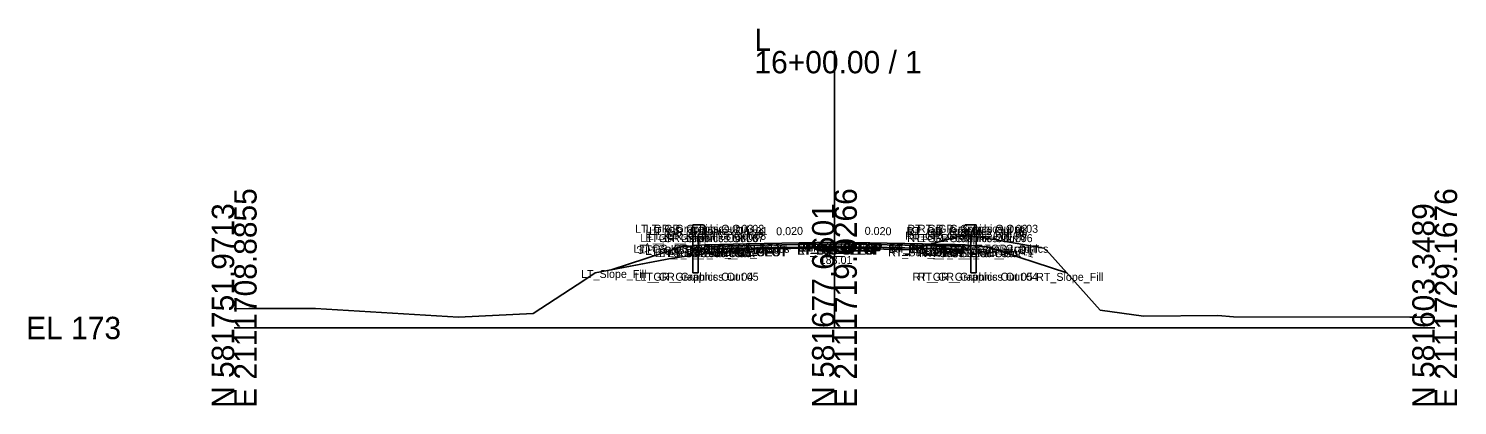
# Model space of a CAD drawing. Extents: x -486 to 1153, y -333 to 9539.
# Drawn here: x -25.7 to 152.8, y 6490.3 to 6537.5 of the extents above; entities that cross this region are included whole.
import ezdxf

# ---------------------------------------------------------------- set-up
doc = ezdxf.new("R2010")
doc.units = 0
for name, color, linetype in [('Default', 7, 'Continuous'), ('Exist Cross Section Cell', 7, 'Continuous'), ('Exist XS Ground Line', 7, 'Continuous'), ('Prop CMT Guardrail Graphics', 7, 'Continuous'), ('Prop CMT Pvmt Course 1', 7, 'Continuous'), ('Prop CMT Pvmt Course 2', 7, 'Continuous'), ('Prop CMT Pvmt Course 3', 7, 'Continuous'), ('Prop CMT Pvmt Surface', 7, 'Continuous'), ('Prop CMT Pvmt Surface Shoulder', 7, 'Continuous'), ('Prop CMT Shld Paved Course 1', 7, 'Continuous'), ('Prop CMT Shld Paved Course 2', 7, 'Continuous'), ('Prop CMT Shld Paved Course 3', 7, 'Continuous'), ('Prop CMT Slope Grass', 7, 'Continuous'), ('Prop CMT Subgrade Earthwork', 7, 'Continuous'), ('Prop XS Earthwork Shape', 7, 'Continuous'), ('Prop XS SE Text', 7, 'Continuous'), ('Prop XS Side Slope Text', 7, 'Continuous'), ('Scratch_Level_0', 7, 'Continuous')]:
    doc.layers.add(name, color=color, linetype=linetype)

msp = doc.modelspace()

# ---------------------------------------------------------------- linework, layer by layer
at = {"layer": 'Exist Cross Section Cell'}
for p, q in [((75, 6500), (75, 6534.66)), ((0, 6500), (75, 6500)), ((75, 6500), (150, 6500))]:
    msp.add_line(p, q, dxfattribs=at)
at = {"layer": 'Exist XS Ground Line'}
for p, q in [((84.43, 6509.78), (90.88, 6511.55)), ((90.88, 6511.55), (93.31, 6511.35)), ((93.31, 6511.35), (101.16, 6509.99)), ((57.72, 6509.17), (65.45, 6509.9)), ((65.45, 6509.9), (66.96, 6509.91)), ((66.96, 6509.91), (74.77, 6510.01)), ((74.77, 6510.01), (76.35, 6509.98)), ((76.35, 6509.98), (84.43, 6509.78)), ((101.16, 6509.99), (101.86, 6509.33)), ((101.86, 6509.33), (108.19, 6502.21)), ((45.1, 6506.88), (54.75, 6508.75)), ((54.75, 6508.75), (57.72, 6509.17)), ((37.37, 6501.8), (43.83, 6506.03)), ((43.83, 6506.03), (45.1, 6506.88)), ((0, 6502.38), (1.82, 6502.42)), ((1.82, 6502.42), (10.14, 6502.43)), ((10.14, 6502.43), (28.03, 6501.34)), ((108.19, 6502.21), (113.61, 6501.48)), ((28.03, 6501.34), (37.37, 6501.8)), ((113.61, 6501.48), (122.91, 6501.58)), ((122.91, 6501.58), (124.87, 6501.41)), ((124.87, 6501.41), (146.9, 6501.34)), ((146.9, 6501.34), (147.49, 6501.35)), ((147.49, 6501.35), (148.14, 6501.36)), ((148.14, 6501.36), (148.51, 6501.35)), ((148.51, 6501.35), (150, 6501.31))]:
    msp.add_line(p, q, dxfattribs=at)
at = {"layer": 'Prop CMT Guardrail Graphics'}
for points in [[(57.3, 6506.91), (57.3, 6512.91)], [(57.3, 6512.91), (58.63, 6512.91), (58.9, 6512.62)], [(92.7, 6512.91), (91.37, 6512.91), (91.1, 6512.62)], [(92.7, 6506.91), (92.7, 6512.91)], [(58.9, 6512.03), (58.63, 6511.74), (57.96, 6511.74)], [(57.96, 6511.74), (57.96, 6506.91)], [(58.9, 6512.62), (58.63, 6512.32)], [(58.63, 6512.32), (58.9, 6512.03)], [(91.1, 6512.62), (91.37, 6512.32)], [(91.37, 6512.32), (91.1, 6512.03)], [(91.1, 6512.03), (91.37, 6511.74), (92.04, 6511.74)], [(92.04, 6511.74), (92.04, 6506.91)], [(57.96, 6506.91), (57.3, 6506.91)], [(92.04, 6506.91), (92.7, 6506.91)]]:
    msp.add_lwpolyline(points, dxfattribs=at)
at = {"layer": 'Prop CMT Pvmt Course 1'}
for points in [[(75, 6510.74), (64, 6510.52)], [(64, 6510.31), (75, 6510.53)], [(64, 6510.52), (64, 6510.31)], [(75, 6510.53), (75, 6510.74)], [(75, 6510.74), (86, 6510.52)], [(75, 6510.53), (75, 6510.74)], [(86, 6510.31), (75, 6510.53)], [(86, 6510.52), (86, 6510.31)]]:
    msp.add_lwpolyline(points, dxfattribs=at)
msp.add_lwpolyline([(75, 6510.53), (75, 6510.61), (75, 6510.61), (75, 6510.53)], close=True, dxfattribs=at)
msp.add_lwpolyline([(75, 6510.53), (75, 6510.61), (75, 6510.61), (75, 6510.53)], close=True, dxfattribs=at)
at = {"layer": 'Prop CMT Pvmt Course 2'}
for points in [[(75, 6510.53), (64, 6510.31)], [(64, 6510.31), (64, 6509.97)], [(64, 6509.97), (75, 6510.19)], [(75, 6510.19), (75, 6510.53)], [(75, 6510.19), (75, 6510.53)], [(75, 6510.53), (86, 6510.31)], [(86, 6509.97), (75, 6510.19)], [(86, 6510.31), (86, 6509.97)]]:
    msp.add_lwpolyline(points, dxfattribs=at)
at = {"layer": 'Prop CMT Pvmt Course 3'}
for points in [[(75, 6510.19), (64, 6509.97)], [(64, 6509.97), (64, 6509.97)], [(75, 6510.19), (75, 6510.19)], [(75, 6510.19), (86, 6509.97)], [(75, 6510.19), (75, 6510.19)], [(86, 6509.97), (86, 6509.97)]]:
    msp.add_lwpolyline(points, dxfattribs=at)
at = {"layer": 'Prop CMT Pvmt Surface'}
for points in [[(75, 6510.74), (64, 6510.52)], [(75, 6510.74), (86, 6510.52)]]:
    msp.add_lwpolyline(points, dxfattribs=at)
at = {"layer": 'Prop CMT Pvmt Surface Shoulder'}
for points in [[(64, 6510.52), (59, 6510.42)], [(86, 6510.52), (91, 6510.42)]]:
    msp.add_lwpolyline(points, dxfattribs=at)
at = {"layer": 'Prop CMT Shld Paved Course 1'}
for points in [[(64, 6510.52), (59, 6510.42), (58.79, 6510.2)], [(58.79, 6510.2), (64, 6510.31)], [(64, 6510.31), (64, 6510.52)], [(86, 6510.52), (91, 6510.42), (91.21, 6510.2)], [(86, 6510.31), (86, 6510.52)], [(91.21, 6510.2), (86, 6510.31)]]:
    msp.add_lwpolyline(points, dxfattribs=at)
at = {"layer": 'Prop CMT Shld Paved Course 2'}
for points in [[(64, 6510.31), (58.79, 6510.2), (58.45, 6509.86)], [(58.45, 6509.86), (64, 6509.97)], [(64, 6509.97), (64, 6510.31)], [(86, 6510.31), (91.21, 6510.2), (91.55, 6509.86)], [(86, 6509.97), (86, 6510.31)], [(91.55, 6509.86), (86, 6509.97)]]:
    msp.add_lwpolyline(points, dxfattribs=at)
at = {"layer": 'Prop CMT Shld Paved Course 3'}
for points in [[(64, 6509.97), (58.45, 6509.86)], [(58.45, 6509.86), (58.45, 6509.86), (58.45, 6509.86)], [(64, 6509.97), (64, 6509.97)], [(86, 6509.97), (91.55, 6509.86)], [(86, 6509.97), (86, 6509.97)], [(91.55, 6509.86), (91.55, 6509.86), (91.55, 6509.86)]]:
    msp.add_lwpolyline(points, dxfattribs=at)
at = {"layer": 'Prop CMT Slope Grass'}
for points in [[(55.9, 6510.17), (47.1, 6507.26)], [(58.9, 6510.41), (55.9, 6510.17)], [(59, 6510.42), (58.9, 6510.41)], [(91, 6510.42), (91.1, 6510.41)], [(91.1, 6510.41), (94.1, 6510.17)], [(94.1, 6510.17), (104.03, 6506.89)]]:
    msp.add_lwpolyline(points, dxfattribs=at)
at = {"layer": 'Prop CMT Subgrade Earthwork'}
for points in [[(58.45, 6509.86), (57.98, 6510.33)], [(64, 6509.97), (58.45, 6509.86)], [(75, 6510.19), (64, 6509.97)], [(75, 6510.19), (86, 6509.97)], [(86, 6509.97), (91.55, 6509.86)], [(91.55, 6509.86), (92.02, 6510.33)]]:
    msp.add_lwpolyline(points, dxfattribs=at)
at = {"layer": 'Prop XS Earthwork Shape'}
for points in [[(93.31, 6511.35), (101.16, 6509.99), (101.86, 6509.33), (104.03, 6506.89), (94.1, 6510.17), (92.02, 6510.33), (91.1, 6510.41), (91, 6510.42), (87.02, 6510.49), (90.88, 6511.55)], [(54.75, 6508.75), (57.72, 6509.17), (65.45, 6509.9), (66.96, 6509.91), (74.77, 6510.01), (76.35, 6509.98), (84.43, 6509.78), (85.19, 6509.99), (75, 6510.19), (64, 6509.97), (58.45, 6509.86), (57.98, 6510.33), (55.9, 6510.17), (47.1, 6507.26)], [(91.55, 6509.86), (92.02, 6510.33), (91.1, 6510.41), (91, 6510.42), (87.02, 6510.49), (85.19, 6509.99), (86, 6509.97)]]:
    msp.add_lwpolyline(points, close=True, dxfattribs=at)

# ---------------------------------------------------------------- texts
at = {"layer": 'Default'}
for s, height, p in [('183.01', 1, (73.16, 6508.01)), ('-', 0.0001, (0, 6500))]:
    msp.add_text(s, height=height, dxfattribs=at).set_placement(p)
at = {"layer": 'Exist Cross Section Cell'}
for s, p in [('L', (65, 6534.66)), ('16+00.00 / 1', (65, 6531.86)), ('EL 173', (-26, 6498.6))]:
    msp.add_text(s, height=2.8, dxfattribs=at).set_placement(p)
for s, p in [('E 2111708.8855', (2.8, 6490)), ('E 2111719.0266', (77.8, 6490)), ('E 2111729.1676', (152.8, 6490)), ('N 581751.9713', (0, 6490)), ('N 581677.6601', (75, 6490)), ('N 581603.3489', (150, 6490))]:
    msp.add_text(s, height=2.8, rotation=90, dxfattribs=at).set_placement(p)
at = {"layer": 'Prop XS SE Text'}
for rotation, p in [(1.1458, (67.73, 6511.59)), (358.8542, (78.77, 6511.66))]:
    msp.add_text('0.020', height=1, rotation=rotation, dxfattribs=at).set_placement(p)
at = {"layer": 'Prop XS Side Slope Text'}
for rotation, p in [(18.2629, (50.51, 6509.18)), (341.7371, (98.04, 6509.36))]:
    msp.add_text('3:1', height=1, rotation=rotation, dxfattribs=at).set_placement(p)
at = {"layer": 'Scratch_Level_0'}
for s, p in [('LT_GR_Graphics Out 03', (50.08, 6511.91)), ('LT_GR_Graphics Out 02', (51.43, 6511.91)), ('RT_GR_Graphics Out 02', (84.11, 6511.91)), ('RT_GR_Graphics Out 03', (85.43, 6511.91)), ('LT_GR_Graphics Out 06', (50.74, 6510.74)), ('LT_GR_Graphics Out 07', (51.39, 6510.74)), ('LT_GR_Graphics Out 09', (51.4, 6511.32)), ('LT_GR_Graphics Out 08', (51.67, 6511.03)), ('LT_GR_Graphics Out 01', (51.85, 6511.62)), ('RT_GR_Graphics Out 08', (83.81, 6511.03)), ('RT_GR_Graphics Out 01', (83.99, 6511.62)), ('RT_GR_Graphics Out 07', (84.07, 6510.74)), ('RT_GR_Graphics Out 09', (84.09, 6511.32)), ('RT_GR_Graphics Out 06', (84.75, 6510.74)), ('LT_GS_OS_GR_Face_Graphics', (49.9, 6509.41)), ('LT_Sub_Trench_Out_DLT', (50.63, 6509.33)), ('LT_GS_OS_CTL', (51.36, 6509.17)), ('LT_Sub_Trench_Out', (52.56, 6508.86)), ('LT_PS3_Shelf_Out', (53.1, 6508.86)), ('LT_PS3_OEOP', (54.23, 6508.86)), ('LT_PS2_OEOP', (54.57, 6509.2)), ('LT_PS1_OEOP', (54.91, 6509.42)), ('LT_PV2_OEOT', (59.75, 6509.31)), ('LT_PV3_OEOT', (59.75, 6508.97)), ('LT_Sub_OEOT', (59.77, 6508.97)), ('LT_PV1_OEOT', (59.87, 6509.52)), ('RT_PV2_OEEOP', (70.33, 6509.53)), ('RT_PV3_OEEOP', (70.33, 6509.19)), ('RT_Sub_OEEOP', (70.36, 6509.19)), ('LT_PV2_OEEOP', (70.39, 6509.53)), ('LT_PV3_OEEOP', (70.39, 6509.19)), ('LT_Sub_OEEOP', (70.42, 6509.19)), ('RT_PV1_OEEOP', (70.45, 6509.61)), ('LT_PV1_OEEOP', (70.51, 6509.61)), ('RT_PV2_IEEOP', (70.71, 6509.53)), ('LT_PV2_IEEOP', (70.77, 6509.53)), ('RT_PV1_IEEOP', (70.83, 6509.61)), ('LT_PV1_IEEOP', (70.89, 6509.61)), ('PV2_PGL', (72.35, 6509.53)), ('PV1_PGL', (72.47, 6509.74)), ('RT_PV2_OEOT', (81.69, 6509.31)), ('RT_PV3_OEOT', (81.69, 6508.97)), ('RT_Sub_OEOT', (81.71, 6508.97)), ('RT_PV1_OEOT', (81.81, 6509.52)), ('RT_GS_OS_GR_Face_Graphics', (82.04, 6509.41)), ('RT_Sub_Trench_Out_DLT', (84.61, 6509.33)), ('RT_Sub_Trench_Out', (85.6, 6508.86)), ('RT_PS3_Shelf_Out', (86.15, 6508.86)), ('RT_PS1_OEOP', (86.85, 6509.42)), ('RT_PS2_OEOP', (86.94, 6509.2)), ('RT_PS3_OEOP', (87.28, 6508.86)), ('RT_GS_OS_CTL', (89.5, 6509.17)), ('LT_Slope_Fill', (43.34, 6506.26)), ('LT_GR_Graphics Out 04', (50.07, 6505.91)), ('LT_GR_Graphics Out 05', (50.74, 6505.91)), ('RT_GR_Graphics Out 05', (84.76, 6505.91)), ('RT_GR_Graphics Out 04', (85.41, 6505.91)), ('RT_Slope_Fill', (100.2, 6505.89))]:
    msp.add_text(s, height=1, dxfattribs=at).set_placement(p)

doc.saveas('drawing.dxf')
